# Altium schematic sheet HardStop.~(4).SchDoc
size A
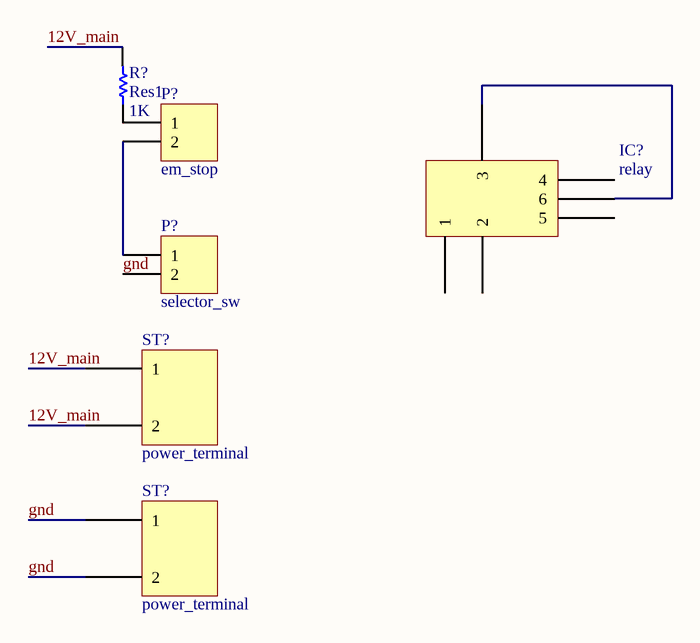
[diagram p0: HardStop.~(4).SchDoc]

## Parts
(Parts that share a designator on the sheet are numbered #1, #2 ... from top to bottom, then left to right.)
IC?  relay  [relay JQX 15F]
P?#1  em_stop  [HDR1X2H]
P?#2  selector_sw  [HDR1X2H]
R?  Res1  value 1K  [AXIAL-0.3]
ST?#1  power_terminal  [screw_terminal_5]
ST?#2  power_terminal  [screw_terminal_5]

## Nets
12V_main: R?.2 ST?#1.1 ST?#1.2
gnd: P?#2.2 ST?#2.1 ST?#2.2
NetIC?_3: IC?.3 IC?.6
NetP?#1_1: P?#1.1 R?.1
NetP?#1_2: P?#1.2 P?#2.1

Not connected (* = marked no-connect by the designer): IC? 1 2 4 5

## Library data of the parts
IC? = relay JQX-15F
P?#1 P?#2 = Header 2H: Header, 2-Pin, Right Angle
R? = Res1: Resistor
ST?#1 ST?#2 = screw_terminal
